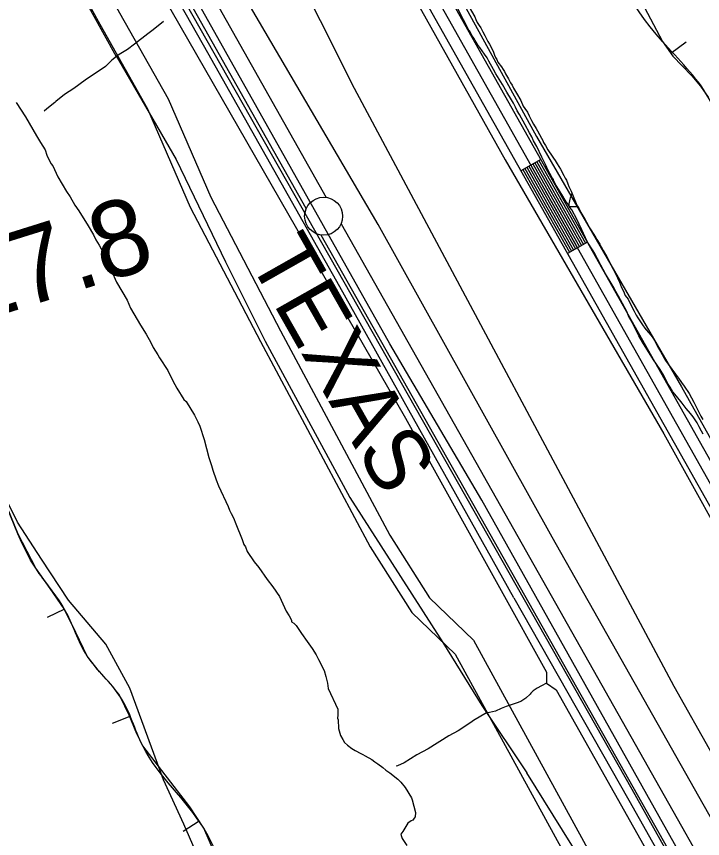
# Model space of a CAD drawing. Extents: x 3187622 to 3225504, y 800805 to 826213.
# Drawn here: x 3193584 to 3194486, y 821717 to 822799 of the extents above; entities that cross this region are included whole.
import ezdxf

# ---------------------------------------------------------------- set-up
doc = ezdxf.new("R2010")
doc.units = 0
for name, color, linetype in [('V-BORW-LINE', 7, 'Continuous'), ('V-LEVE-TOET', 7, 'Continuous'), ('V-RAIL-IDEN', 7, 'Continuous'), ('V-RAIL-TRAK', 7, 'Continuous'), ('V-ROAD-CNTR', 7, 'Continuous'), ('V-SITE-VEGE', 7, 'Continuous'), ('V-SURV-IDEN', 7, 'Continuous'), ('V-SURV-LINE', 7, 'Continuous'), ('V-TOPO-SHOR', 7, 'Continuous'), ('V-WETL-SWMP', 7, 'Continuous')]:
    doc.layers.add(name, color=color, linetype=linetype)

msp = doc.modelspace()

# ---------------------------------------------------------------- linework, layer by layer
at = {"layer": 'V-BORW-LINE'}
for p, q in [((3194444.7, 822750.9), (3194465.1, 822765.5)), ((3193646.9, 822019), (3193624.4, 822008)), ((3193732.9, 821877.7), (3193709.7, 821868.4)), ((3193824.3, 821739.5), (3193803.2, 821726.1))]:
    msp.add_line(p, q, dxfattribs=at)
for points in [[(3194387, 822855.3), (3194433.8, 822766.2), (3194447.6, 822747), (3194472.2, 822720.8), (3194483.9, 822707.4), (3194494, 822692.8)], [(3193855.2, 821672.7), (3193830.2, 821730.3), (3193812.1, 821758.6), (3193750, 821838.8), (3193742.1, 821854.5), (3193732.2, 821879.3), (3193720.8, 821903.1), (3193710.5, 821917.1), (3193692.9, 821936.5), (3193676.9, 821957.1), (3193661.9, 821988.2), (3193646.8, 822019.2), (3193628.1, 822045.9), (3193609.2, 822072.6), (3193585.9, 822117.5), (3193556.8, 822188.5)]]:
    msp.add_lwpolyline(points, dxfattribs=at)
for points in [[(3194746.7, 824428.2), (3194770.2, 824392.5), (3194839.9, 824358.9), (3194843.7, 824354.2), (3194822.9, 824352.6), (3194805.6, 824354.5), (3194783.8, 824344), (3194808, 824310.6), (3194860.9, 824111.5), (3194890.3, 824049), (3194919.9, 824022.8), (3194936.8, 823993.7), (3194967.5, 823945.1), (3194990.2, 823878.8), (3195044.4, 823786.8), (3195063.9, 823718), (3195053.2, 823688.8), (3195056.3, 823616.2), (3195008.6, 823396.2), (3194962.2, 823257.3), (3194949.6, 823254.7), (3194916.1, 823270.5), (3194892.6, 823394.4), (3194818.7, 823675.4), (3194764.8, 823725), (3194732.1, 823768.5), (3194627.7, 823861.2), (3194598.2, 823922.8), (3194572.9, 824011.1), (3194544.8, 824024.5), (3194532.2, 824018.4), (3194535.7, 823972.4), (3194544.3, 823935.6), (3194590.6, 823765.3), (3194640.4, 823657.8), (3194680.8, 823529.9), (3194719.1, 823459), (3194750.6, 823333.9), (3194793.9, 823142.5), (3194772.9, 823135.8), (3194752.4, 823099.7), (3194748.5, 823050.4), (3194776.1, 822932.3), (3194811.1, 822874.8), (3194830.8, 822797.1), (3194831.1, 822768.9), (3194796.7, 822656), (3194757.4, 822452), (3194745.4, 822448.1), (3194718.1, 822363.5), (3194698.9, 822349.8), (3194685.3, 822355.9), (3194657.8, 822398.5), (3194530.3, 822600.2), (3194494, 822692.8), (3194433.8, 822766.2), (3194343.3, 822945.9), (3194289.3, 823081), (3194253.9, 823096.6), (3194220.4, 823161), (3194213.4, 823170.5), (3194173.2, 823254.5)], [(3193316.9, 822598.6), (3193335.2, 822540.6), (3193410.3, 822427.7), (3193431.9, 822364.3), (3193469.1, 822310), (3193521.5, 822255.9), (3193609.2, 822072.6), (3193646.8, 822019.2), (3193676.9, 821957.1), (3193720.8, 821903.1), (3193750, 821838.8), (3193830.2, 821730.3), (3193879.7, 821614.9), (3193980.5, 821434.8), (3194001.3, 821375.3), (3194045.6, 821322.9), (3194255.4, 820971.9), (3194278.3, 820910.6), (3194299.8, 820853), (3194335.6, 820798.4), (3194443.8, 820680.4), (3194483.4, 820494.4), (3194474.8, 820430), (3194362.4, 820338.7), (3194243.4, 820273.7), (3194115.5, 820232.8), (3193985.1, 820192.2), (3193871, 820096.9), (3193700.8, 819982), (3193642.2, 819950.8), (3193574.5, 819997.4), (3193482.7, 820109.4), (3193411.4, 820226.4), (3193461, 820288.3), (3193516, 820325.3), (3193569.4, 820370.5), (3193689.7, 820437.3), (3193809.3, 820477.2), (3193921.8, 820552.8), (3193973.7, 820602), (3193968.2, 820665.5), (3193943.7, 820740.3), (3193889.6, 820861.5), (3193818.7, 820974.4), (3193871.9, 821026.9), (3193893.2, 821093.5), (3193831.6, 821288.3), (3193762, 821415.9), (3193682.1, 821525.7), (3193580.7, 821633.2), (3193582.1, 821571.4), (3193675.7, 821399.4), (3193689.4, 821337.7), (3193683, 821270), (3193666, 821201.1), (3193594.8, 821238.9), (3193552.5, 821298.8), (3193499, 821351.2), (3193535.6, 821424), (3193485.3, 821613.1), (3193426.4, 821662.5), (3193356.9, 821777.8), (3193308.4, 821900.5), (3193294.3, 821963), (3193279.7, 822022.1), (3193265.1, 822081.6), (3193249.6, 822013.9), (3193262.2, 821951.7), (3193210.3, 822002.4), (3193038.4, 822236.4), (3192901.1, 822477.4), (3192892.6, 822538.2), (3192940.3, 822603.2), (3192988.9, 822662), (3193107.6, 822723.1), (3193158.6, 822772.1), (3193217.2, 822790.6), (3193249.5, 822765), (3193290.2, 822685.8), (3193316.9, 822598.6)]]:
    msp.add_spline(points, degree=3, dxfattribs=at)
at = {"layer": 'V-LEVE-TOET'}
for points in [[(3193584.3, 822982.9), (3193715.2, 822746.5), (3193715.3, 822746.3)], [(3193894.5, 822971.4), (3194028.2, 822704.5), (3194448.5, 821917.6)], [(3193715.3, 822746.3), (3193717.9, 822741.8), (3193794.1, 822610.8), (3193858.9, 822476), (3193911.1, 822371.7), (3194022.5, 822165.9), (3194144.7, 821975), (3194195.9, 821891.8), (3194255.3, 821803.4)], [(3194448.5, 821917.6), (3194600, 821648.8), (3194730.3, 821412.1), (3194889.3, 821132.9), (3195058.8, 820825.9), (3195075.3, 820785.1), (3195080.3, 820773.1), (3195087.5, 820766.1), (3195094.5, 820766.2), (3195101.6, 820771.9), (3195107.6, 820782.7), (3195113.8, 820796.7), (3195176.6, 820853), (3195190.5, 820860.2), (3195219.9, 820873.4), (3195237.6, 820893.1), (3195245.9, 820920.5), (3195264, 820997.9), (3195322.1, 821260.9), (3195389.9, 821526.1), (3195492.2, 821898.4)], [(3195509.7, 819625.3), (3195482.6, 819673.9), (3195459.2, 819713.2), (3195438.4, 819750.9), (3195422, 819777.4), (3195404.1, 819806.5), (3195388.5, 819832.8), (3195369.9, 819862.9), (3195294.5, 819981.2), (3195273.4, 820017.6), (3195233.7, 820077.8), (3195218.6, 820104.8), (3195199.4, 820136.6), (3195173.6, 820178.4), (3195142.1, 820229.4), (3195073.8, 820350.4), (3195014.1, 820460), (3194933, 820615.4), (3194826.9, 820807.9), (3194726, 820985.8), (3194603, 821208.6), (3194474, 821433.9), (3194336.7, 821672), (3194255.3, 821803.4)]]:
    msp.add_lwpolyline(points, dxfattribs=at)
at = {"layer": 'V-RAIL-TRAK'}
for points in [[(3194238.4, 822033.7), (3194009.1, 822443.2), (3193835.4, 822751.2), (3193727.3, 822943)], [(3194238.4, 822033.7), (3194389.3, 821767.4), (3194710.7, 821197.3), (3195003.1, 820677), (3195353.4, 820056.4), (3195586, 819645), (3195933.8, 819028.7), (3196235.6, 818491.2), (3196397.8, 818207.7), (3196539.2, 817967.3), (3196658.3, 817767.6), (3196713.5, 817682.2), (3196876.7, 817422.2), (3197092.7, 817079.2), (3197323.6, 816712.3)]]:
    msp.add_lwpolyline(points, dxfattribs=at)
at = {"layer": 'V-ROAD-CNTR'}
for p, q in [((3194273.8, 822610.8), (3194247.6, 822596)), ((3194335.1, 822501.8), (3194308.9, 822487.1))]:
    msp.add_line(p, q, dxfattribs=at)
for points in [[(3193942.7, 823199), (3195097.4, 821147.5)], [(3193916.5, 823184.3), (3195071.3, 821132.7)], [(3193929.6, 823191.6), (3195084.4, 821140.1)], [(3193546.7, 823116.4), (3193719.6, 822803.7), (3193783.2, 822690.8), (3193839.5, 822561.1), (3193931.2, 822385.2), (3194075.1, 822116.1), (3194127.2, 822033.7), (3194185.2, 821977.8), (3194639.7, 821147.1), (3195029.5, 820446.4), (3195072.9, 820348.7), (3195192.1, 820158.7), (3195238.4, 820041.1), (3195343.7, 819857.8), (3195584.5, 819427.5)], [(3193520.4, 823101.8), (3193693.4, 822789.1), (3193756.3, 822677.4), (3193812.4, 822548.2), (3193904.7, 822371.2), (3194049.2, 822101), (3194103.8, 822014.6), (3194161.1, 821959.4), (3194613.5, 821132.6), (3195002.6, 820433), (3195046.3, 820334.6), (3195165.2, 820145.1), (3195211.3, 820028), (3195317.6, 819843), (3195558.5, 819412.5)], [(3193654.2, 823085.5), (3194393.6, 821781.9), (3194932.5, 820818.5), (3195643.8, 819559.4), (3196039.6, 818863.6), (3196103.7, 818747.1), (3196200.1, 818577.4), (3196283.3, 818430.9), (3196415.9, 818198), (3196513.3, 818033.2), (3196633.1, 817833.5), (3197048.3, 817166.1), (3197473.1, 816486.2), (3198091.5, 815496.5), (3198625.8, 814645.6), (3198678.1, 814561.9), (3198728.8, 814484.2), (3198769.6, 814407.5), (3198909.8, 814179.8), (3198995, 814024.9)], [(3194255.5, 822600.5), (3194316.8, 822491.5)], [(3194258.1, 822601.9), (3194319.4, 822493)], [(3194260.7, 822603.4), (3194322, 822494.5)], [(3194263.3, 822604.9), (3194324.6, 822495.9)], [(3194265.9, 822606.3), (3194327.2, 822497.4)], [(3194268.5, 822607.8), (3194329.8, 822498.9)], [(3194271.1, 822609.3), (3194332.5, 822500.4)], [(3194250.2, 822597.5), (3194311.5, 822488.6)], [(3194252.8, 822599), (3194314.2, 822490.1)]]:
    msp.add_lwpolyline(points, dxfattribs=at)
at = {"layer": 'V-SITE-VEGE'}
for p, q in [((3193583.3, 822685.9), (3193595.6, 822666.8)), ((3193595.6, 822666.8), (3193610.1, 822642.1)), ((3193610.1, 822642.1), (3193615.5, 822633.3)), ((3193615.5, 822633.3), (3193621.6, 822623.7)), ((3193621.6, 822623.7), (3193623.9, 822616.6)), ((3193623.9, 822616.6), (3193629.2, 822605.5)), ((3193629.2, 822605.5), (3193631.5, 822602.3)), ((3193631.5, 822602.3), (3193638.3, 822587.9)), ((3193638.3, 822587.9), (3193649.8, 822568.8)), ((3193649.8, 822568.8), (3193654.4, 822561.6)), ((3193654.4, 822561.6), (3193660.5, 822550.5)), ((3193660.5, 822550.5), (3193665.9, 822543.3)), ((3193665.9, 822543.3), (3193678.2, 822523.3)), ((3193678.2, 822523.3), (3193685.1, 822511.4)), ((3193685.1, 822511.4), (3193688.1, 822505)), ((3193688.1, 822505), (3193692.7, 822497.8)), ((3193692.7, 822497.8), (3193698.1, 822488.3)), ((3193698.1, 822488.3), (3193701.1, 822484.3)), ((3193701.1, 822484.3), (3193708.7, 822464.4)), ((3193708.7, 822464.4), (3193715.5, 822449.3)), ((3193715.5, 822449.3), (3193729.3, 822425.4)), ((3193729.3, 822425.4), (3193733.8, 822415.1)), ((3193733.8, 822415.1), (3193746.8, 822392.8)), ((3193746.8, 822392.8), (3193754.5, 822380.8)), ((3193754.5, 822380.8), (3193760.6, 822369.7)), ((3193760.6, 822369.7), (3193763.6, 822363.3)), ((3193763.6, 822363.3), (3193769.8, 822353.7)), ((3193769.8, 822353.7), (3193772.1, 822349.7)), ((3193772.1, 822349.7), (3193782.8, 822333)), ((3193782.8, 822333), (3193789.7, 822319.4)), ((3193789.7, 822319.4), (3193795, 822309.9)), ((3193795, 822309.9), (3193804.2, 822294.7)), ((3193804.2, 822294.7), (3193807.3, 822292.3)), ((3193807.3, 822292.3), (3193818, 822274)), ((3193818, 822274), (3193822.6, 822265.2)), ((3193822.6, 822265.2), (3193824.9, 822259.7)), ((3193824.9, 822259.7), (3193830.9, 822242.2)), ((3193830.9, 822242.2), (3193836.8, 822218.4)), ((3193836.8, 822218.4), (3193840.5, 822208.1)), ((3193840.5, 822208.1), (3193842, 822201.8)), ((3193842, 822201.8), (3193846.5, 822189.1)), ((3193846.5, 822189.1), (3193849.5, 822181.2)), ((3193585.4, 822133.5), (3193558.6, 822187.1)), ((3193849.5, 822181.2), (3193862.4, 822154.1)), ((3193862.4, 822154.1), (3193863.9, 822149.3)), ((3193863.9, 822149.3), (3193866.2, 822144.6)), ((3193866.2, 822144.6), (3193869.3, 822139)), ((3193869.3, 822139), (3193872.3, 822131.1)), ((3193616.7, 822084.4), (3193585.4, 822133.5)), ((3193872.3, 822131.1), (3193880.6, 822110.4)), ((3193880.6, 822110.4), (3193882.8, 822104.1)), ((3193882.8, 822104.1), (3193885.1, 822100.9)), ((3193885.1, 822100.9), (3193887.4, 822094.5)), ((3193887.4, 822094.5), (3193896.6, 822080.9)), ((3193652.4, 822030.7), (3193616.7, 822084.4)), ((3193896.6, 822080.9), (3193902.8, 822073.7)), ((3193902.8, 822073.7), (3193913.6, 822057.8)), ((3193913.6, 822057.8), (3193921.3, 822048.2)), ((3193921.3, 822048.2), (3193929.7, 822035.4)), ((3193701.5, 821972.7), (3193652.4, 822030.7)), ((3193929.7, 822035.4), (3193938.8, 822016.3)), ((3193938.8, 822016.3), (3193942.7, 822009.9)), ((3193942.7, 822009.9), (3193945.7, 822004.3)), ((3193945.7, 822004.3), (3193945.7, 822002)), ((3193945.7, 822002), (3193948.8, 822000.3)), ((3193948.8, 822000.3), (3193951.9, 821997.1)), ((3193951.9, 821997.1), (3193958.8, 821986.8)), ((3193958.8, 821986.8), (3193966.5, 821976.4)), ((3193732.8, 821914.6), (3193701.5, 821972.7)), ((3193966.5, 821976.4), (3193972.7, 821966.8)), ((3193972.7, 821966.8), (3193978, 821958.8)), ((3193978, 821958.8), (3193981.1, 821952.5)), ((3193981.1, 821952.5), (3193988.7, 821938.1)), ((3193988.7, 821938.1), (3193990.9, 821930.2)), ((3193990.9, 821930.2), (3193993.1, 821921.5)), ((3193993.1, 821921.5), (3193993.8, 821914.4)), ((3193777.4, 821794), (3193732.8, 821914.6)), ((3193993.8, 821914.4), (3194006.7, 821887.3)), ((3194006.7, 821887.3), (3194006.8, 821879.2)), ((3194006.8, 821879.2), (3194006.4, 821875.2)), ((3194006.4, 821875.2), (3194006.9, 821873.2)), ((3194006.9, 821873.2), (3194007.4, 821861.5)), ((3194007.4, 821861.5), (3194010.3, 821852.6)), ((3194010.3, 821852.6), (3194013.2, 821847)), ((3194013.2, 821847), (3194015.6, 821843.3)), ((3194015.6, 821843.3), (3194019.3, 821839.7)), ((3194019.3, 821839.7), (3194025, 821835.3)), ((3194025, 821835.3), (3194029.5, 821832.6)), ((3194029.5, 821832.6), (3194036.8, 821829)), ((3194036.8, 821829), (3194039.6, 821827.4)), ((3194039.6, 821827.4), (3194042.5, 821825.8)), ((3194042.5, 821825.8), (3194051.4, 821821)), ((3194051.4, 821821), (3194055.5, 821817.8)), ((3194055.5, 821817.8), (3194059.1, 821815)), ((3194059.1, 821815), (3194065.7, 821810.3)), ((3194065.7, 821810.3), (3194069.7, 821806.7)), ((3194069.7, 821806.7), (3194075, 821803.5)), ((3194075, 821803.5), (3194085.6, 821795.1)), ((3193804.2, 821735.9), (3193777.4, 821794)), ((3194085.6, 821795.1), (3194089.7, 821791.1)), ((3194089.7, 821791.1), (3194095.4, 821783.9)), ((3194095.4, 821783.9), (3194103.6, 821770.6)), ((3194103.6, 821770.6), (3194104.5, 821767.8)), ((3194104.5, 821767.8), (3194108.7, 821751.2)), ((3194108.3, 821745.6), (3194107.1, 821743.5)), ((3194108.7, 821751.2), (3194108.3, 821745.6)), ((3193835.4, 821664.4), (3193804.2, 821735.9)), ((3194098.7, 821737), (3194092.3, 821726)), ((3194103.1, 821740.3), (3194098.7, 821737)), ((3194105.5, 821741.1), (3194103.1, 821740.3)), ((3194107.1, 821743.5), (3194105.5, 821741.1)), ((3194092.3, 821726), (3194089.5, 821722.8)), ((3194089.5, 821722.8), (3194090, 821720.7)), ((3194090, 821720.7), (3194091.2, 821717.1)), ((3194091.2, 821717.1), (3194097.4, 821707.5))]:
    msp.add_line(p, q, dxfattribs=at)
at = {"layer": 'V-SURV-LINE'}
for points in [[(3193965.1, 822546.1), (3192901.9, 824431.9)], [(3192936.4, 824431.8), (3193991.3, 822560.8)], [(3194010.9, 822526.1), (3195297.4, 820248.2)], [(3195271.3, 820233.4), (3193984.8, 822511.3)]]:
    msp.add_lwpolyline(points, dxfattribs=at)
msp.add_circle((3193988, 822536.1), 25, dxfattribs=at)
at = {"layer": 'V-TOPO-SHOR'}
for points in [[(3192870.5, 824432.6), (3193272, 823719.6), (3193655.5, 823037.4), (3194095.7, 822270.4), (3194281, 821935.8), (3194281, 821921.4), (3194293.9, 821912.6), (3194523, 821505.9), (3194839.6, 820947.3), (3195012.1, 820643.6), (3195336.4, 820069.6), (3195480.5, 819812.2), (3195732.8, 819366.9)], [(3196669.7, 817789), (3196420.1, 818211.1), (3196348, 818329.5), (3196021.1, 818916.4), (3195920.7, 819106.9), (3195681.3, 819521.3), (3195459.9, 819917.7), (3195341.5, 820128.8), (3194986.3, 820754.3), (3194837, 821019.4), (3194610.5, 821418.4), (3194502.4, 821616.6), (3194445.8, 821717), (3194196.1, 822162.3), (3194075.1, 822368.2), (3193771.4, 822908.7), (3193596.3, 823217.6), (3193297.8, 823753), (3193179.4, 823964.1), (3192906.5, 824437.7)], [(3195107.3, 820738.8), (3195071.3, 820751.7), (3194754.7, 821292.3), (3194566.8, 821621.7), (3194288.8, 822113.4), (3194059.7, 822525.2), (3193743.1, 823065.8), (3193650.4, 823235.6), (3193457.3, 823567.7), (3193228.3, 823971.8), (3192963.1, 824435.1)], [(3193919.5, 823665.7), (3193784.3, 823601.2), (3193771.4, 823588.3), (3193758.5, 823570.3), (3193761.1, 823554.8), (3193768.8, 823536.8), (3193781.7, 823513.6), (3193817.7, 823446.7), (3193838.3, 823441.6), (3193848.6, 823441.6), (3193861.5, 823441.6), (3193866.6, 823439), (3193866.6, 823433.9), (3193853.7, 823418.4), (3193843.5, 823405.5), (3193843.5, 823397.8), (3193853.7, 823377.2), (3193979.9, 823166.2), (3194268.2, 822641), (3194458.6, 822311.6), (3194777.8, 821742.7), (3194960.6, 821415.8), (3195056.3, 821245.3)], [(3193707, 823539.4), (3193961.9, 823083.8), (3194227, 822610.2), (3194435.5, 822249.8), (3194790.7, 821608.9), (3194893.7, 821433.8), (3195158.8, 820973.1)], [(3193777.1, 822792.3), (3193763.5, 822781.6), (3193756.6, 822776.2), (3193739.3, 822762.6), (3193729.7, 822755.4), (3193719.1, 822749.2), (3193715.3, 822746.3)], [(3193715.3, 822746.3), (3193709.3, 822741.7), (3193700.8, 822733.2), (3193674.2, 822715.1), (3193659.5, 822704.4), (3193647.1, 822696.3), (3193635.7, 822686.9), (3193634.3, 822685.6), (3193623.6, 822677.4), (3193620.1, 822674.2)], [(3194281, 821921.4), (3194274.8, 821917.7), (3194268.7, 821914.6), (3194267.6, 821914.1), (3194263.5, 821911.4), (3194260.5, 821908), (3194259.9, 821906.9), (3194254, 821901.5), (3194247.3, 821897.4), (3194241.4, 821895.1), (3194228.2, 821890.5), (3194221.4, 821887.9), (3194214, 821884.6), (3194206.2, 821882.8), (3194202.3, 821882.5), (3194185.3, 821872.1), (3194181.5, 821869.6), (3194164.9, 821858.8), (3194152.8, 821852.1), (3194125.3, 821834.9), (3194110.8, 821827), (3194102.1, 821821.6), (3194094, 821816.5), (3194085, 821812.7), (3194083.2, 821812.1)]]:
    msp.add_lwpolyline(points, dxfattribs=at)
at = {"layer": 'V-WETL-SWMP'}
for p, q in [((3194290.6, 822583), (3194290.6, 822585.2)), ((3194311.2, 822549.1), (3194322.1, 822549.1))]:
    msp.add_line(p, q, dxfattribs=at)
for points in [[(3194105.9, 822937.6), (3194186.7, 822798.7), (3194188.3, 822794.9), (3194190, 822791.2), (3194192.6, 822787.1), (3194194.7, 822783.9), (3194197.5, 822778.8), (3194199.9, 822774.2), (3194202.2, 822769.8), (3194204.1, 822766.1), (3194206.2, 822762.4), (3194211, 822753.2), (3194212.9, 822748.1), (3194214.3, 822744.9), (3194215.7, 822742.2), (3194217.3, 822738.9), (3194221.8, 822732.7), (3194224.2, 822729.3), (3194225.8, 822726.5), (3194227.2, 822723.7), (3194231, 822717.1), (3194233.8, 822711.8), (3194235.9, 822708.5), (3194237.6, 822704.8), (3194241.8, 822698.2), (3194247.5, 822688.3), (3194250.6, 822681.1), (3194252.7, 822678.1), (3194256, 822673), (3194258.5, 822668.2), (3194261.6, 822662), (3194264.2, 822657.4), (3194267.7, 822651.4), (3194269.4, 822648.4), (3194274.6, 822638.7), (3194276.2, 822635.9), (3194277.4, 822633.2), (3194279.8, 822629.3), (3194283.1, 822623.3), (3194288.7, 822615.2), (3194290.6, 822612.5), (3194292.5, 822609.5), (3194295.1, 822604.9), (3194299.5, 822598), (3194304.2, 822589.7), (3194305.9, 822586.2), (3194307.3, 822583.4), (3194309.2, 822578.8), (3194310.6, 822575.1), (3194313.5, 822569.1), (3194317, 822560.1), (3194320.3, 822553), (3194322, 822549.3), (3194324.1, 822545.8), (3194326.5, 822541), (3194331.4, 822532), (3194333.8, 822528.1), (3194335.4, 822525.3), (3194337.8, 822521), (3194339.4, 822518), (3194345.8, 822508.5), (3194347.4, 822505.5), (3194351.2, 822499.1), (3194353.1, 822495.8), (3194355.7, 822491), (3194360.4, 822482.7)], [(3194487.2, 822249), (3194485.3, 822253), (3194482, 822259), (3194479.2, 822264), (3194474.2, 822271.9), (3194470.7, 822276.5), (3194465.1, 822282.9), (3194459.5, 822290), (3194452.2, 822299), (3194447.5, 822305), (3194443.8, 822310.9), (3194441.4, 822314.9), (3194438.6, 822319.9), (3194435.5, 822326.6), (3194430.6, 822334.4), (3194422.1, 822347.1), (3194407.3, 822370.1), (3194402.8, 822378.7), (3194396.9, 822390.2), (3194393.8, 822396.6), (3194389.1, 822404.9), (3194386.8, 822410.5), (3194381.3, 822421.3), (3194378.7, 822426.1), (3194376.1, 822430.7), (3194372.6, 822437), (3194370.3, 822441.3), (3194366.3, 822448), (3194358.7, 822460.2), (3194352.6, 822471.5), (3194351.2, 822474.3), (3194348.3, 822479.8), (3194344.6, 822487), (3194341.5, 822492), (3194336.1, 822500.6), (3194332.3, 822507.7), (3194330, 822513.2), (3194327.6, 822518.3), (3194324.3, 822525.7), (3194321.2, 822532.4), (3194314.4, 822544.4), (3194312.3, 822547.1), (3194309.4, 822552.2), (3194307.1, 822554.9), (3194301.2, 822564.8), (3194293.9, 822576.6), (3194291.8, 822580.7), (3194285.7, 822592.5), (3194283.5, 822596.4), (3194280.2, 822603.3), (3194275, 822613.9), (3194268.4, 822628), (3194264.2, 822635.4), (3194261.8, 822640.4), (3194259, 822645.7), (3194252.9, 822656.6), (3194245.6, 822669.9), (3194242.7, 822675), (3194240.4, 822679.6), (3194237.8, 822684.7), (3194235.2, 822689.5), (3194229.1, 822699.4), (3194223.2, 822709.6), (3194218.9, 822716.7), (3194214.7, 822723.6), (3194211.6, 822729.1), (3194205.5, 822740.2), (3194202.9, 822744.6), (3194199.4, 822749.6), (3194196.6, 822753.6), (3194193.3, 822758.2), (3194191.4, 822760.9), (3194187.2, 822767.4), (3194185.8, 822770.1), (3194183.4, 822773.6), (3194179.9, 822780), (3194179.4, 822780.3), (3194156.6, 822824.8)], [(3194360.4, 822482.7), (3194362.2, 822479.7), (3194364.4, 822475.1), (3194366, 822472.3), (3194368.9, 822466.6), (3194372.9, 822459), (3194374.5, 822455.1), (3194377.1, 822449.1), (3194380, 822442.1), (3194382.3, 822437.3), (3194384.9, 822431.8), (3194388.5, 822426.7), (3194390.3, 822423), (3194392, 822419.8), (3194393.4, 822417), (3194396.5, 822411), (3194399.3, 822406), (3194401.4, 822402.3), (3194403.1, 822399.7), (3194407.5, 822393.1), (3194410.4, 822388.9), (3194412.5, 822386.4), (3194415.5, 822383.2), (3194418.8, 822379), (3194421.1, 822375.8), (3194424.2, 822371), (3194427.3, 822364.8), (3194431, 822358.1), (3194436.2, 822349.3), (3194437.9, 822346.3), (3194441.1, 822341.5), (3194446.1, 822334.8), (3194451, 822328.2), (3194454.8, 822322.9), (3194459, 822317.1), (3194462.3, 822312.5), (3194468.8, 822302.6), (3194475.2, 822291.1), (3194478.7, 822284.2), (3194480.9, 822279.8), (3194484.4, 822272.9), (3194487, 822268.5)]]:
    msp.add_lwpolyline(points, dxfattribs=at)
msp.add_arc((3194345.8, 822549.5), 35.2, 152.027, 178.9154, dxfattribs=at)

# ---------------------------------------------------------------- texts
at = {"layer": 'V-RAIL-IDEN'}
msp.add_text('TEXAS', height=83, rotation=299.5586, dxfattribs=at).set_placement((3193887.3, 822480.7))
at = {"layer": 'V-SURV-IDEN'}
msp.add_text('1348+17.8', height=100, rotation=17.4235, dxfattribs=at).set_placement((3193163.3, 822280.4))

doc.saveas('drawing.dxf')
